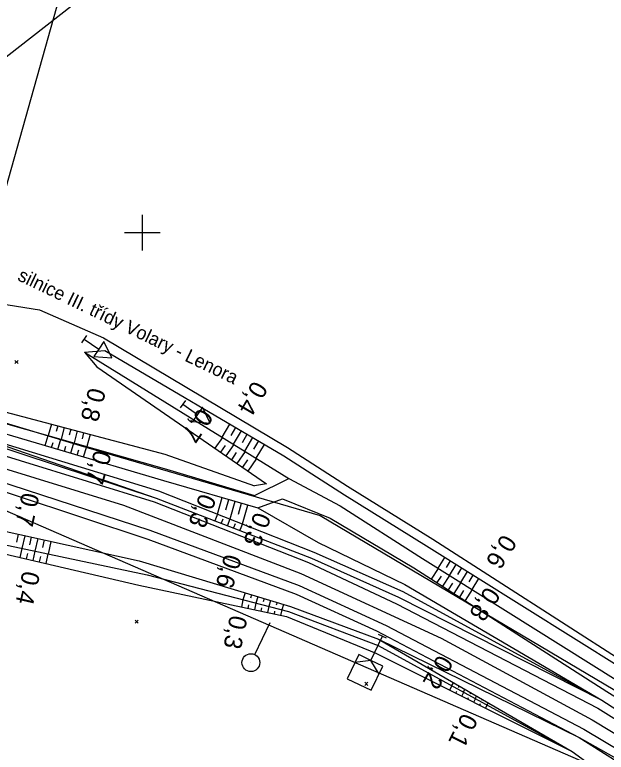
# Model space of a CAD drawing. Extents: x -804899 to -803847, y -1165742 to -1164942.
# Drawn here: x -804714.3 to -804647.9, y -1165158.3 to -1165075.5 of the extents above; entities that cross this region are included whole.
import ezdxf

# ---------------------------------------------------------------- set-up
doc = ezdxf.new("R2010")
doc.units = 0
for name, color, linetype in [('0381KM061-064P - Vrstva 1', 7, 'Continuous'), ('0381KM061-064P - Vrstva 36', 7, 'Continuous'), ('0381KM061-064P - Vrstva 4', 7, 'Continuous'), ('0381KM061-064P - Vrstva 48', 7, 'Continuous'), ('0381KM061-064P - Vrstva 49', 7, 'Continuous'), ('0381KM061-064P - Vrstva 51', 7, 'Continuous'), ('0381KM061-064P - Vrstva 55', 7, 'Continuous'), ('0381KM061-064P - Vrstva 7', 7, 'Continuous'), ('0381KM061-064P - Vrstva 8', 7, 'Continuous'), ('hran DP - hran DP', 7, 'Continuous'), ('krizky_1000 - Vrstva 1', 7, 'Continuous')]:
    doc.layers.add(name, color=color, linetype=linetype)

msp = doc.modelspace()

# ---------------------------------------------------------------- linework, layer by layer
at = {"layer": '0381KM061-064P - Vrstva 1'}
for points in [[(-804748.021, -1165118.722), (-804737.69, -1165120.695), (-804722.056, -1165124.431), (-804702.108, -1165130.565), (-804682.19, -1165138.236), (-804666.439, -1165145.5)], [(-804666.439, -1165145.5), (-804649.478, -1165154.654), (-804645.137, -1165157.269), (-804633.704, -1165164.378), (-804619.363, -1165173.737)]]:
    msp.add_lwpolyline(points, dxfattribs=at)
at = {"layer": '0381KM061-064P - Vrstva 36'}
for p, q in [((-804687.368, -1165147.341), (-804685.621, -1165143.743)), ((-804687.805, -1165148.241), (-804687.805, -1165148.241))]:
    msp.add_line(p, q, dxfattribs=at)
msp.add_circle((-804687.805, -1165148.241), 1, dxfattribs=at)
at = {"layer": '0381KM061-064P - Vrstva 4'}
for points in [[(-804755.733, -1165115.927), (-804748.168, -1165116.905), (-804721.253, -1165123.253), (-804698.663, -1165130.219), (-804681.332, -1165136.993), (-804671.473, -1165141.648), (-804648.845, -1165153.359), (-804638.113, -1165160.035), (-804624.479, -1165168.696), (-804602.557, -1165183.067), (-804574.466, -1165201.721), (-804542.719, -1165222.837), (-804507.36, -1165246.549), (-804477.085, -1165266.816), (-804448.754, -1165285.875), (-804421.182, -1165304.145), (-804392.893, -1165323.086), (-804369.849, -1165338.366), (-804348.858, -1165352.041), (-804325.134, -1165367.981), (-804299.324, -1165385.271), (-804266.052, -1165407.314), (-804234.277, -1165428.598)], [(-804755.733, -1165115.927), (-804748.032, -1165116.485), (-804721.047, -1165122.361), (-804698.438, -1165129.771), (-804680.982, -1165136.504), (-804671.213, -1165140.894), (-804648.415, -1165152.455), (-804637.551, -1165159.434), (-804624.035, -1165168.294), (-804602.248, -1165182.377), (-804573.745, -1165201.202), (-804542.465, -1165222.561), (-804507.059, -1165246.026), (-804476.473, -1165266.236), (-804448.309, -1165285.076), (-804421.024, -1165303.102), (-804392.59, -1165322.59), (-804369.414, -1165337.648), (-804348.678, -1165351.592), (-804324.758, -1165367.42), (-804298.904, -1165384.417), (-804265.65, -1165406.497), (-804234.045, -1165428.038)], [(-804760.257, -1165118.798), (-804748.359, -1165120.009), (-804721.794, -1165126.004), (-804699.133, -1165133.383), (-804682.383, -1165139.582), (-804672.624, -1165144.091), (-804650.427, -1165155.704), (-804639.382, -1165162.287), (-804626.131, -1165170.888), (-804604.367, -1165185.52), (-804576.364, -1165204.152)], [(-804760.257, -1165118.798), (-804748.388, -1165120.746), (-804721.772, -1165126.976), (-804699.376, -1165134.382), (-804682.716, -1165140.57), (-804673.684, -1165144.668), (-804650.962, -1165156.638), (-804639.654, -1165163.015), (-804626.635, -1165171.43)]]:
    msp.add_lwpolyline(points, dxfattribs=at)
at = {"layer": '0381KM061-064P - Vrstva 48'}
for p, q in [((-804710.208, -1165121.482), (-804710.55, -1165122.773)), ((-804709.483, -1165121.674), (-804709.656, -1165122.326)), ((-804708.758, -1165121.866), (-804709.107, -1165123.183)), ((-804691.025, -1165122.956), (-804690.153, -1165121.472)), ((-804690.035, -1165122.751), (-804689.507, -1165121.852)), ((-804710.9, -1165123.888), (-804710.569, -1165122.768)), ((-804708.033, -1165122.058), (-804708.209, -1165122.723)), ((-804707.308, -1165122.25), (-804707.664, -1165123.593)), ((-804706.583, -1165122.441), (-804706.763, -1165123.12)), ((-804705.858, -1165122.633), (-804706.221, -1165124.004)), ((-804689.75, -1165123.744), (-804688.86, -1165122.232)), ((-804688.752, -1165123.528), (-804688.214, -1165122.611)), ((-804710.181, -1165124.101), (-804710.014, -1165123.537)), ((-804709.462, -1165124.314), (-804709.126, -1165123.178)), ((-804708.024, -1165124.74), (-804707.683, -1165123.588)), ((-804690.995, -1165122.975), (-804691.835, -1165124.194)), ((-804688.473, -1165124.532), (-804687.568, -1165122.991)), ((-804687.47, -1165124.304), (-804686.922, -1165123.371)), ((-804708.743, -1165124.527), (-804708.574, -1165123.955)), ((-804707.305, -1165124.953), (-804707.133, -1165124.373)), ((-804706.586, -1165125.166), (-804706.24, -1165123.998)), ((-804690.701, -1165123.869), (-804691.217, -1165124.619)), ((-804689.717, -1165123.764), (-804690.6, -1165125.045)), ((-804687.198, -1165125.32), (-804686.275, -1165123.751)), ((-804689.44, -1165124.683), (-804689.982, -1165125.47)), ((-804688.44, -1165124.553), (-804689.364, -1165125.896)), ((-804687.162, -1165125.342), (-804688.129, -1165126.747)), ((-804688.179, -1165125.497), (-804688.747, -1165126.321)), ((-804691.547, -1165131.569), (-804691.015, -1165129.727)), ((-804690.626, -1165131.081), (-804690.295, -1165129.934)), ((-804690.146, -1165132.121), (-804689.575, -1165130.142)), ((-804689.209, -1165131.578), (-804688.855, -1165130.35)), ((-804688.745, -1165132.674), (-804688.135, -1165130.557)), ((-804691.549, -1165131.568), (-804691.838, -1165132.317)), ((-804690.966, -1165132.141), (-804691.138, -1165132.587)), ((-804690.154, -1165132.118), (-804690.438, -1165132.857)), ((-804689.569, -1165132.687), (-804689.739, -1165133.126)), ((-804688.758, -1165132.669), (-804689.039, -1165133.396)), ((-804714.085, -1165134.709), (-804713.894, -1165133.839)), ((-804713.479, -1165135.443), (-804713.162, -1165133.999)), ((-804712.619, -1165135.023), (-804712.43, -1165134.16)), ((-804712.012, -1165135.752), (-804711.698, -1165134.32)), ((-804711.153, -1165135.336), (-804710.966, -1165134.481)), ((-804710.545, -1165136.061), (-804710.234, -1165134.641)), ((-804713.522, -1165135.434), (-804713.754, -1165136.434)), ((-804712.883, -1165135.995), (-804713.024, -1165136.604)), ((-804712.054, -1165135.743), (-804712.294, -1165136.773)), ((-804710.587, -1165136.053), (-804710.833, -1165137.112)), ((-804711.418, -1165136.316), (-804711.563, -1165136.943)), ((-804666.78, -1165137.662), (-804666.009, -1165136.43)), ((-804665.836, -1165137.568), (-804665.373, -1165136.828)), ((-804666.778, -1165137.663), (-804667.545, -1165138.86)), ((-804665.51, -1165138.459), (-804664.738, -1165137.226)), ((-804664.566, -1165138.364), (-804664.103, -1165137.624)), ((-804666.451, -1165138.543), (-804666.914, -1165139.264)), ((-804665.507, -1165138.46), (-804666.283, -1165139.669)), ((-804664.24, -1165139.255), (-804663.468, -1165138.022)), ((-804663.296, -1165139.16), (-804662.832, -1165138.42)), ((-804665.184, -1165139.345), (-804665.651, -1165140.074)), ((-804664.237, -1165139.257), (-804665.02, -1165140.479)), ((-804662.97, -1165140.052), (-804662.197, -1165138.818)), ((-804663.917, -1165140.146), (-804664.389, -1165140.883)), ((-804662.966, -1165140.054), (-804663.758, -1165141.288)), ((-804688.459, -1165140.411), (-804688.691, -1165141.18)), ((-804687.741, -1165140.629), (-804687.853, -1165140.998)), ((-804687.023, -1165140.846), (-804687.238, -1165141.555)), ((-804686.305, -1165141.064), (-804686.408, -1165141.403)), ((-804688.838, -1165142.005), (-804688.663, -1165141.187)), ((-804688.104, -1165142.161), (-804688.02, -1165141.768)), ((-804687.371, -1165142.318), (-804687.21, -1165141.563)), ((-804685.588, -1165141.281), (-804685.784, -1165141.931)), ((-804684.87, -1165141.499), (-804684.964, -1165141.809)), ((-804684.152, -1165141.716), (-804684.331, -1165142.306)), ((-804686.638, -1165142.475), (-804686.56, -1165142.113)), ((-804685.904, -1165142.631), (-804685.756, -1165141.938)), ((-804685.171, -1165142.788), (-804685.1, -1165142.457)), ((-804684.437, -1165142.945), (-804684.302, -1165142.314)), ((-804665.469, -1165151.341), (-804665.225, -1165150.852)), ((-804665.072, -1165150.477), (-804665.274, -1165150.825)), ((-804664.423, -1165150.853), (-804664.519, -1165151.019)), ((-804664.799, -1165151.676), (-804664.682, -1165151.444)), ((-804664.128, -1165152.012), (-804663.907, -1165151.571)), ((-804663.774, -1165151.229), (-804663.957, -1165151.543)), ((-804663.126, -1165151.606), (-804663.212, -1165151.754)), ((-804663.457, -1165152.347), (-804663.353, -1165152.139)), ((-804662.786, -1165152.683), (-804662.59, -1165152.289)), ((-804662.477, -1165151.982), (-804662.639, -1165152.262)), ((-804661.828, -1165152.358), (-804661.904, -1165152.49)), ((-804662.116, -1165153.019), (-804662.023, -1165152.834)), ((-804661.445, -1165153.354), (-804661.272, -1165153.008)), ((-804661.179, -1165152.735), (-804661.322, -1165152.981))]:
    msp.add_line(p, q, dxfattribs=at)
at = {"layer": '0381KM061-064P - Vrstva 49'}
for p, q in [((-804713.936, -1165114.691), (-804714.29, -1165114.337)), ((-804713.936, -1165114.337), (-804714.29, -1165114.691)), ((-804700.458, -1165143.82), (-804700.812, -1165143.466)), ((-804700.458, -1165143.466), (-804700.812, -1165143.82)), ((-804673.479, -1165145.601), (-804650.962, -1165156.638)), ((-804674.661, -1165150.801), (-804675.015, -1165150.447)), ((-804674.661, -1165150.447), (-804675.015, -1165150.801))]:
    msp.add_line(p, q, dxfattribs=at)
for points in [[(-804755.733, -1165115.927), (-804751.237, -1165112.247), (-804747.153, -1165112.992), (-804720.555, -1165118.745), (-804697.457, -1165124.856)], [(-804706.484, -1165113.41), (-804704.188, -1165113.224), (-804684.109, -1165125.024), (-804677.287, -1165129.42), (-804668.091, -1165135.126)], [(-804706.484, -1165113.41), (-804683.561, -1165127.566)], [(-804706.484, -1165113.41), (-804705.101, -1165115.056), (-804686.067, -1165128.167), (-804687.408, -1165128.395)], [(-804754.423, -1165115.02), (-804748.035, -1165114.39), (-804721.192, -1165119.749), (-804697.281, -1165126.544)], [(-804755.733, -1165115.927), (-804747.853, -1165115.391), (-804738.732, -1165116.754), (-804720.925, -1165120.918), (-804697.629, -1165127.819)], [(-804738.732, -1165116.754), (-804737.496, -1165118.134), (-804721.084, -1165121.979), (-804698.174, -1165128.955), (-804680.733, -1165135.834), (-804670.748, -1165140.269), (-804648.415, -1165152.455)], [(-804721.084, -1165121.979), (-804698.438, -1165129.771), (-804680.982, -1165136.504), (-804671.213, -1165140.894), (-804648.415, -1165152.455)], [(-804766.835, -1165123.914), (-804764.887, -1165122.959), (-804750.44, -1165127.42), (-804724.293, -1165131.559), (-804700.35, -1165136.808), (-804683.355, -1165141.958), (-804673.479, -1165145.601), (-804651.73, -1165158.215)], [(-804766.318, -1165124.347), (-804750.308, -1165128.296), (-804724.802, -1165133.057), (-804699.443, -1165138.401), (-804683.582, -1165142.5), (-804673.524, -1165146.323), (-804651.73, -1165158.215)], [(-804697.457, -1165124.856), (-804687.408, -1165128.395)], [(-804697.281, -1165126.544), (-804687.391, -1165129.497), (-804683.561, -1165127.566)], [(-804697.629, -1165127.819), (-804687.02, -1165130.879), (-804684.245, -1165129.866), (-804678.905, -1165132.048), (-804669.513, -1165137.598)], [(-804683.561, -1165127.566), (-804677.796, -1165130.644), (-804668.529, -1165136.565)], [(-804687.02, -1165130.879), (-804680.246, -1165134.762), (-804670.528, -1165139.48)], [(-804724.988, -1165133.826), (-804700.388, -1165139.537), (-804683.823, -1165143.076), (-804673.785, -1165147.18), (-804651.73, -1165158.215)], [(-804668.091, -1165135.126), (-804646.081, -1165148.913), (-804635.338, -1165155.788), (-804621.983, -1165164.4), (-804599.675, -1165178.865), (-804570.229, -1165197.632), (-804539.044, -1165217.403), (-804503.793, -1165239.318), (-804473.21, -1165259.252), (-804445.018, -1165277.367), (-804416.303, -1165295.604), (-804385.233, -1165314.873), (-804342.844, -1165342.159), (-804322.164, -1165355.5), (-804292.151, -1165374.603), (-804262.581, -1165393.439), (-804234.254, -1165411.433)], [(-804668.529, -1165136.565), (-804646.506, -1165150.377), (-804635.748, -1165157.189), (-804622.879, -1165165.281), (-804600.738, -1165179.997), (-804571.058, -1165199.051), (-804539.913, -1165219.229), (-804504.853, -1165241.382), (-804474.067, -1165260.594), (-804445.752, -1165278.863), (-804417.384, -1165297.085), (-804386.131, -1165316.291), (-804343.677, -1165343.22), (-804323.054, -1165356.811), (-804293.414, -1165375.484), (-804263.448, -1165394.428), (-804234.677, -1165412.775)], [(-804669.513, -1165137.598), (-804647.83, -1165151.5), (-804636.874, -1165158.276), (-804626.963, -1165165.564)], [(-804670.528, -1165139.48), (-804648.415, -1165152.455)], [(-804650.962, -1165156.638), (-804629.948, -1165169.869)], [(-804651.73, -1165158.215), (-804641.239, -1165165.822), (-804629.212, -1165174.279), (-804606.382, -1165188.592), (-804578.691, -1165207.384), (-804546.551, -1165228.405), (-804509.403, -1165252.767), (-804482.019, -1165272.353), (-804454.071, -1165289.87), (-804424.017, -1165310.321)]]:
    msp.add_lwpolyline(points, dxfattribs=at)
at = {"layer": '0381KM061-064P - Vrstva 51'}
for p, q in [((-804706.26, -1165111.529), (-804706.816, -1165112.361)), ((-804695.159, -1165118.831), (-804695.731, -1165119.651))]:
    msp.add_line(p, q, dxfattribs=at)
for points in [[(-804728.9, -1165105.899), (-804711.537, -1165108.671), (-804704.349, -1165111.804), (-804683.685, -1165124.094), (-804676.948, -1165128.427), (-804667.361, -1165134.407), (-804645.714, -1165148.297), (-804634.703, -1165155.23), (-804621.633, -1165163.621), (-804599.185, -1165178.232), (-804569.67, -1165197.161), (-804538.422, -1165216.767), (-804503.409, -1165238.938), (-804472.822, -1165258.548), (-804444.565, -1165276.404), (-804415.818, -1165294.725), (-804384.702, -1165314.566), (-804342.586, -1165341.716), (-804321.799, -1165355.02), (-804291.771, -1165374.224), (-804262.453, -1165392.961)], [(-804706.538, -1165111.945), (-804704.876, -1165113.057), (-804705.432, -1165113.888), (-804703.421, -1165114.03), (-804704.32, -1165112.226), (-804704.876, -1165113.057)], [(-804695.445, -1165119.241), (-804693.805, -1165120.385), (-804694.377, -1165121.205), (-804692.369, -1165121.386), (-804693.233, -1165119.565), (-804693.805, -1165120.385)]]:
    msp.add_lwpolyline(points, dxfattribs=at)
at = {"layer": '0381KM061-064P - Vrstva 55'}
msp.add_lwpolyline([(-804834.02, -1165173.21), (-804777.95, -1165165.95), (-804761.65, -1165133.49), (-804755.48, -1165121.19), (-804751.26, -1165114.04), (-804741.92, -1165100.8), (-804736.13, -1165096.49), (-804701.79, -1165069.72), (-804628.296, -1165012.443)], dxfattribs=at)
at = {"layer": '0381KM061-064P - Vrstva 7'}
for p, q in [((-804672.58, -1165145.506), (-804673.48, -1165145.072)), ((-804674.332, -1165147.992), (-804673.03, -1165145.289))]:
    msp.add_line(p, q, dxfattribs=at)
for points in [[(-804674.332, -1165147.992), (-804675.684, -1165147.341), (-804676.986, -1165150.043), (-804674.283, -1165151.345), (-804672.981, -1165148.643), (-804674.332, -1165147.992)], [(-804673.416, -1165149.545), (-804674.332, -1165147.992), (-804676.118, -1165148.243)]]:
    msp.add_lwpolyline(points, dxfattribs=at)
at = {"layer": '0381KM061-064P - Vrstva 8'}
msp.add_line((-804722.504, -1165120.543), (-804702.468, -1165049.266), dxfattribs=at)
at = {"layer": 'hran DP - hran DP'}
for p, q in [((-804735.44, -1165115.31), (-804706.98, -1165123.89)), ((-804706.98, -1165123.89), (-804680.02, -1165131.72)), ((-804647.39, -1165160.7), (-804728.07, -1165125.68)), ((-804680.02, -1165131.72), (-804619.47, -1165167.61))]:
    msp.add_line(p, q, dxfattribs=at)
at = {"layer": 'krizky_1000 - Vrstva 1'}
for points in [[(-804700, -1165098), (-804700, -1165102)], [(-804702, -1165100), (-804698, -1165100)]]:
    msp.add_lwpolyline(points, dxfattribs=at)

# ---------------------------------------------------------------- texts
at = {"layer": '0381KM061-064P - Vrstva 48'}
for s, rotation, p in [('0,4', 239.55815, (-804687.526, -1165116.493)), ('0,8', 255.18088, (-804705.988, -1165117.275)), ('0,7', 235.44015, (-804693.565, -1165119.56)), ('0,7', 253.49907, (-804705.33, -1165124.268)), ('0,7', 257.63472, (-804713.481, -1165129.055)), ('0,3', 248.47496, (-804693.495, -1165129.137)), ('0,3', 248.90774, (-804687.351, -1165131.224)), ('0,6', 237.93709, (-804659.527, -1165133.711)), ('0,6', 253.1416, (-804690.713, -1165135.939)), ('0,4', 256.93005, (-804713.398, -1165137.845)), ('0,8', 237.33414, (-804661.357, -1165139.592)), ('0,3', 257.94044, (-804690.126, -1165142.822)), ('0,2', 239.88709, (-804666.721, -1165147.239)), ('0,1', 243.41936, (-804664.024, -1165153.782))]:
    msp.add_text(s, height=2, rotation=rotation, dxfattribs=at).set_placement(p)
at = {"layer": '0381KM061-064P - Vrstva 51'}
msp.add_text('silnice III. třídy Volary - Lenora', height=1.5, rotation=334.25776, dxfattribs=at).set_placement((-804714.102, -1165105.286))

doc.saveas('drawing.dxf')
